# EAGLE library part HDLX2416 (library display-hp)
LED DISPLAY 4-character dot matrix
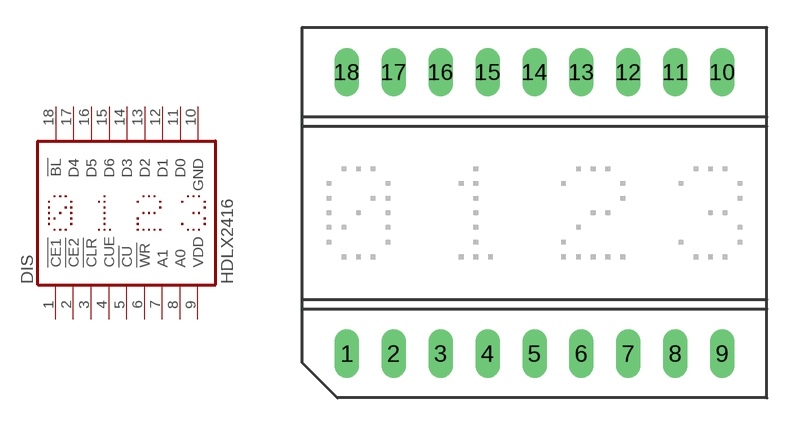
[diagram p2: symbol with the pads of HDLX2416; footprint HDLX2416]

Designator prefix DIS

## HDLX2416 (OC_FARNELL: unknown; OC_NEWARK: unknown)  [HDLX2416]
1  !CE1  in
2  !CE2  in
3  !CLR  in
4  CUE  in
5  !CU  in
6  !WR  in
7  A1  in
8  A0  in
9  VDD  pwr
10  GND  pwr
11  D0  in
12  D1  in
13  D2  in
14  D3  in
15  D6  in
16  D5  in
17  D4  in
18  !BL  in

## Footprint HDLX2416 (pad centres in mm)
LED DISPLAY 5-mm 4 character dot matrix without decimal point
drill 0.813 long: 1 -10.16,-7.62; 2 -7.62,-7.62; 3 -5.08,-7.62; 4 -2.54,-7.62; 5 0,-7.62; 6 2.54,-7.62; 7 5.08,-7.62; 8 7.62,-7.62; 9 10.16,-7.62; 10 10.16,7.62; 11 7.62,7.62; 12 5.08,7.62; 13 2.54,7.62; 14 0,7.62; 15 -2.54,7.62; 16 -5.08,7.62; 17 -7.62,7.62; 18 -10.16,7.62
